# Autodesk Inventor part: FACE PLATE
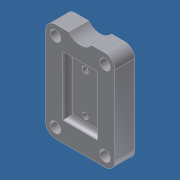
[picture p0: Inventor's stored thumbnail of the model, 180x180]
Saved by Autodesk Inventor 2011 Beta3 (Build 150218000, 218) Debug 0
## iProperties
Shininess: 64.0
Length Units: 11272
Angle Units: 11279
Time Units: 11290
Mass Units: 11286
Length Display Precision: 3
Angle Display Precision: 2
Compacted: True
Part Number: FACE PLATE
Document SubType Name: Modeling
Created: 2003-11
Designer: Autodesk, Inc.
Manufacturer: Standard
Standards Organization: Custom
Mass: 239.386 g
Surface Area: 93.2455 cm^2
Volume: 30.4562 cm^3
Density: 7.86 g/cm^3
Material: Steel, Mild
Density: 0.0
Volumn: 0.0
Area: 0.0
PropertySet Name: Model Information
Control State: 0
Master: False
Checked Out: False
Author: Autodesk, Inc.
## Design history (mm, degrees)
sketch "Sketch1"
  geometry: L1 (0, 0)-(44.45, 0); L2 (44.45, 0)-(44.45, 63.5); L3 (44.45, 63.5)-(0, 63.5); L4 (0, 63.5)-(0, 0)
  constraints: 8 end point, 2 parallel, 1 horizontal, 1 perpendicular
  dimensions: "d0" = 44.45 distance between parallel lines of L2 L4; "d1" = 63.5 distance of L1.end L2.end
extrude "Extrusion1" new body sketch "Sketch1" distance "d2" = 12.7; taper "d3" = 0 deg
sketch "Sketch2"
  geometry: L1 (0, 0)-(0, 63.5) reference; L2 (44.45, 0)-(0, 0) reference; L3 (44.45, 63.5)-(44.45, 0) reference; L4 (0, 63.5)-(44.45, 63.5) reference; L5 (0, 31.75)-(44.45, 31.75); 4 further points
  constraints: 2 end point, 2 midpoint, 2 symmetric about line
  dimensions: "d4" = 6.35 distance from line of point (6.35, 57.15) L4; "d5" = 6.35 distance from line of L4 point (38.1, 57.15); "d6" = 6.35 distance from line of L1 point (6.35, 57.15); "d7" = 6.35 distance from line of L3 point (38.1, 57.15)
hole "Hole1" sketch "Sketch2" at (6.35, 57.15), (38.1, 57.15), (6.35, 6.35), (38.1, 6.35) diameter "d8" = 6.731; stored, may be unused: countersink angle "d12" = 82 deg, drill point angle "d14" = 118 deg; dims "d9" = 12.7, "d10" = 9.525, "d11" = 6.35, "d13" = 19.05
fillet "Fillet1" dims "d15" = 6.35
sketch "Sketch3"
  geometry: L1 (11.125, 50.8)-(33.35, 50.8); L2 (33.35, 50.8)-(33.35, 12.7); L3 (33.35, 12.7)-(11.125, 12.7); L4 (11.125, 12.7)-(11.125, 50.8); L5 (44.45, 57.15)-(44.45, 6.35) reference; L6 (38.1, 0)-(6.35, 0) reference
  constraints: 8 end point, 2 parallel, 1 horizontal, 1 perpendicular
  dimensions: "d16" = 11.0998 distance between parallel lines of L5 L2; "d17" = 22.225 distance between parallel lines of L2 L4; "d18" = 12.7 distance between parallel lines of L6 L3; "d19" = 38.1 distance between parallel lines of L3 L1
extrude "Extrusion2" cut sketch "Sketch3" distance "d20" = 3.175; taper "d21" = 0 deg
sketch "Sketch4"
  geometry: L1 (14.3, 15.875)-(14.3, 47.625) reference; L2 (30.175, 47.625)-(30.175, 15.875) reference; L3 (14.3, 47.625)-(30.175, 47.625) reference; L4 (14.3, 31.75)-(30.175, 31.75); L5 (30.175, 15.875)-(14.3, 15.875) reference; C1 r 3.365 at (6.35, 57.15) reference; 1 further point
  constraints: 2 end point, 2 midpoint
  dimensions: "d23" = 15.875 horizontal distance of C1.centre point (22.225, 44.45); "d24" = 12.7 vertical distance of point (22.225, 44.45) C1.centre
hole "Hole2" sketch "Sketch4" at (22.225, 44.45) diameter "d25" = 3.9624; stored, may be unused: countersink angle "d29" = 82 deg, drill point angle "d31" = 118 deg; dims "d26" = 12.7, "d27" = 9.525, "d28" = 6.35, "d30" = 19.05
workplane "Work Plane1"
mirror "Mirror1"
sketch "Sketch5"
  geometry: C1 r 9.274 at (-22.225, 69.17)
  constraints: 1 centre point
extrude "Extrusion3" cut sketch "Sketch5" stored distance "d33" = 25.4; taper "d34" = 0 deg
fillet "Fillet3" dims "d39" = 3.175
body "Solid1"
node "Projected Loop1"
other parameters: "d32" = -31.75, "d35" = 0, "d36" = 0, "d37" = 0, "d38" = 0
